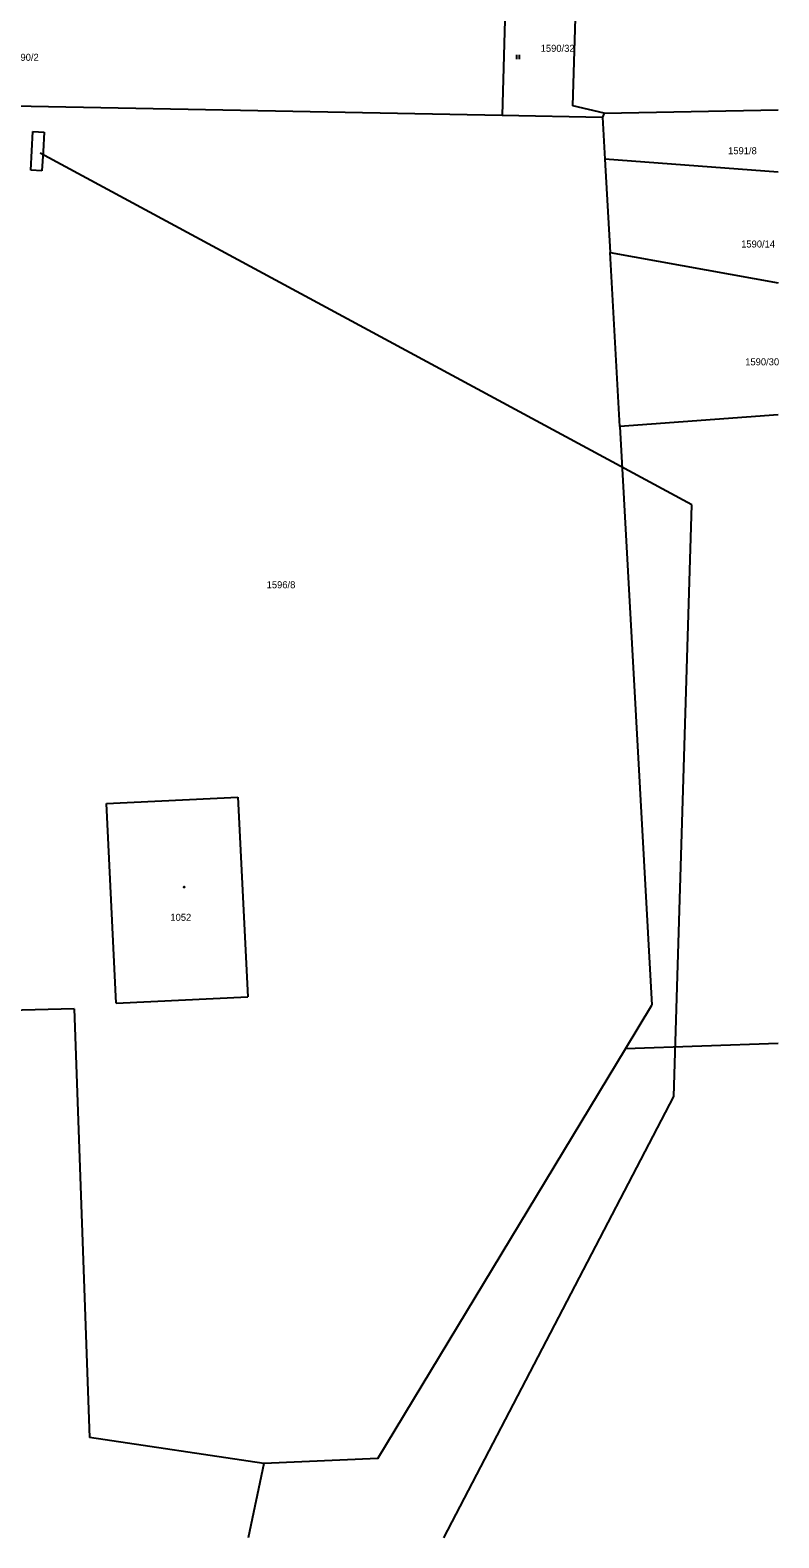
# Model space of a CAD drawing. Extents: x -866624 to -866276, y -1050208 to -1049940.
# Drawn here: x -866329.4 to -866276, y -1050208.1 to -1050100.7 of the extents above; entities that cross this region are included whole.
import ezdxf

# ---------------------------------------------------------------- set-up
doc = ezdxf.new("R2010")
doc.units = 0
for name, color, linetype in [('Default', 7, 'Continuous'), ('Hranice', 7, 'Continuous'), ('Hranice další', 7, 'Continuous'), ('Hranice-budov', 7, 'Continuous'), ('Parcela-pozemkova', 7, 'Continuous'), ('Parcela-stavebni', 7, 'Continuous'), ('znacky-budov', 7, 'Continuous'), ('Znacky-kultury', 7, 'Continuous')]:
    doc.layers.add(name, color=color, linetype=linetype)

# ---------------------------------------------------------------- blocks, each defined once
blk = doc.blocks.new('p_louka')
at = {"layer": 'Default'}
for p, q in [((-0.47, 0.72), (-0.47, -0.78)), ((0.53, 0.72), (0.53, -0.78))]:
    blk.add_line(p, q, dxfattribs=at)
blk = doc.blocks.new('s_zdena')
at = {"layer": 'Default'}
blk.add_circle((0, 0), 0.175, dxfattribs=at)
for start, end in [(0, 180), (180, 0)]:
    blk.add_arc((0, 0), 0.0875, start, end, dxfattribs=at)

msp = doc.modelspace()

# ---------------------------------------------------------------- linework, layer by layer
at = {"layer": 'Hranice'}
for p, q in [((-866295.47, -1050097.36), (-866295.74, -1050106.73)), ((-866290.72, -1050106.06), (-866290.46, -1050097.5)), ((-866332.54, -1050106.03), (-866295.74, -1050106.73)), ((-866295.74, -1050106.73), (-866288.59, -1050106.87)), ((-866288.47, -1050106.58), (-866290.72, -1050106.06)), ((-866288.47, -1050106.58), (-866288.59, -1050106.87)), ((-866288.47, -1050106.58), (-866276.08, -1050106.34)), ((-866288.59, -1050106.87), (-866288.42, -1050109.87)), ((-866288.42, -1050109.87), (-866288.05, -1050116.52)), ((-866276.08, -1050110.8), (-866288.42, -1050109.87)), ((-866288.05, -1050116.52), (-866276.08, -1050118.68)), ((-866287.36, -1050128.91), (-866288.05, -1050116.52)), ((-866276.08, -1050128.08), (-866287.36, -1050128.91)), ((-866287.36, -1050128.91), (-866285.08, -1050170.17)), ((-866323.92, -1050155.79), (-866314.58, -1050155.34)), ((-866323.24, -1050170.03), (-866323.92, -1050155.79)), ((-866314.58, -1050155.34), (-866313.85, -1050169.58)), ((-866323.24, -1050170.03), (-866313.85, -1050169.58)), ((-866286.96, -1050173.29), (-866285.08, -1050170.17)), ((-866326.22, -1050170.44), (-866341.12, -1050170.83)), ((-866326.22, -1050170.44), (-866325.15, -1050200.99)), ((-866304.59, -1050202.49), (-866286.96, -1050173.29)), ((-866276.08, -1050172.9), (-866286.96, -1050173.29)), ((-866312.73, -1050202.84), (-866325.15, -1050200.99)), ((-866304.59, -1050202.49), (-866312.73, -1050202.84)), ((-866312.73, -1050202.84), (-866313.83, -1050208.15))]:
    msp.add_line(p, q, dxfattribs=at)
at = {"layer": 'Hranice další'}
for p, q in [((-866329.32, -1050110.65), (-866329.17, -1050107.9)), ((-866329.17, -1050107.9), (-866328.38, -1050107.94)), ((-866328.38, -1050107.94), (-866328.45, -1050109.32)), ((-866282.23, -1050134.51), (-866328.65, -1050109.44)), ((-866328.45, -1050109.32), (-866328.53, -1050110.69)), ((-866328.53, -1050110.69), (-866329.32, -1050110.65)), ((-866283.51, -1050176.69), (-866282.23, -1050134.51)), ((-866299.91, -1050208.15), (-866283.51, -1050176.69))]:
    msp.add_line(p, q, dxfattribs=at)
at = {"layer": 'Hranice-budov'}
for p, q in [((-866323.92, -1050155.79), (-866314.58, -1050155.34)), ((-866323.24, -1050170.03), (-866323.92, -1050155.79)), ((-866314.58, -1050155.34), (-866313.85, -1050169.58)), ((-866323.24, -1050170.03), (-866313.85, -1050169.58))]:
    msp.add_line(p, q, dxfattribs=at)

# ---------------------------------------------------------------- block references
at = {"layer": 'znacky-budov', "xscale": 0.2, "yscale": 0.20000000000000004}
msp.add_blockref('s_zdena', (-866318.39, -1050161.75), dxfattribs=at)
at = {"layer": 'Znacky-kultury', "xscale": 0.2, "yscale": 0.20000000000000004}
msp.add_blockref('p_louka', (-866294.63, -1050102.57), dxfattribs=at)

# ---------------------------------------------------------------- texts
at = {"layer": 'Parcela-pozemkova'}
for s, p in [('1590/2', (-866330.8, -1050102.85)), ('1590/32', (-866293, -1050102.21)), ('1591/8', (-866279.65, -1050109.51)), ('1590/14', (-866278.72, -1050116.16)), ('1590/30', (-866278.43, -1050124.56)), ('1596/8', (-866312.52, -1050140.45))]:
    msp.add_text(s, height=0.5, dxfattribs=at).set_placement(p)
at = {"layer": 'Parcela-stavebni'}
msp.add_text('1052', height=0.5, dxfattribs=at).set_placement((-866319.38, -1050164.16))

doc.saveas('drawing.dxf')
